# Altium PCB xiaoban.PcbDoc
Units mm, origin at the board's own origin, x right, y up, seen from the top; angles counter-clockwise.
Board outline 80.34 x 99.39 mm, 2 copper layers (Top Layer, Bottom Layer); 120 components, 25 nets, 528 pads, 380 vias.
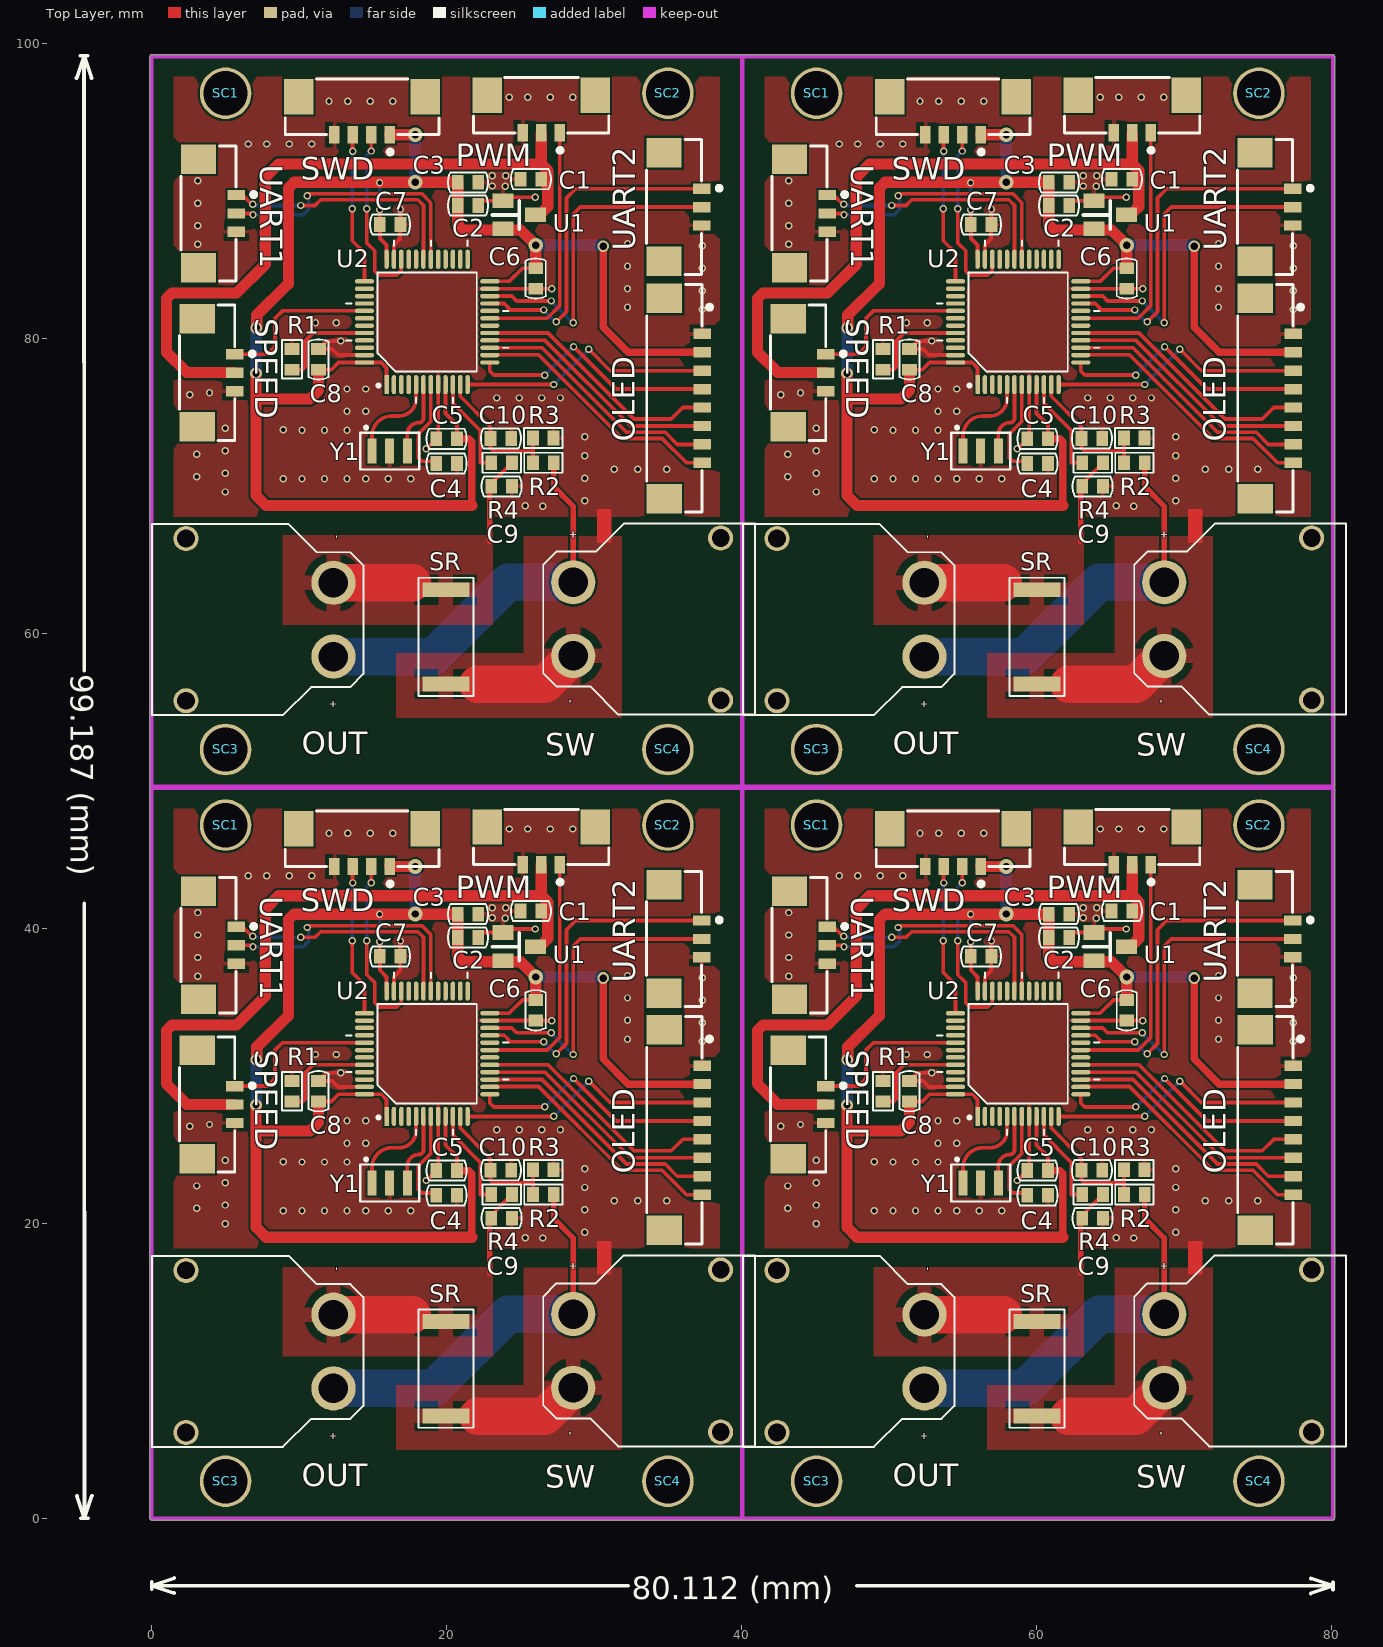
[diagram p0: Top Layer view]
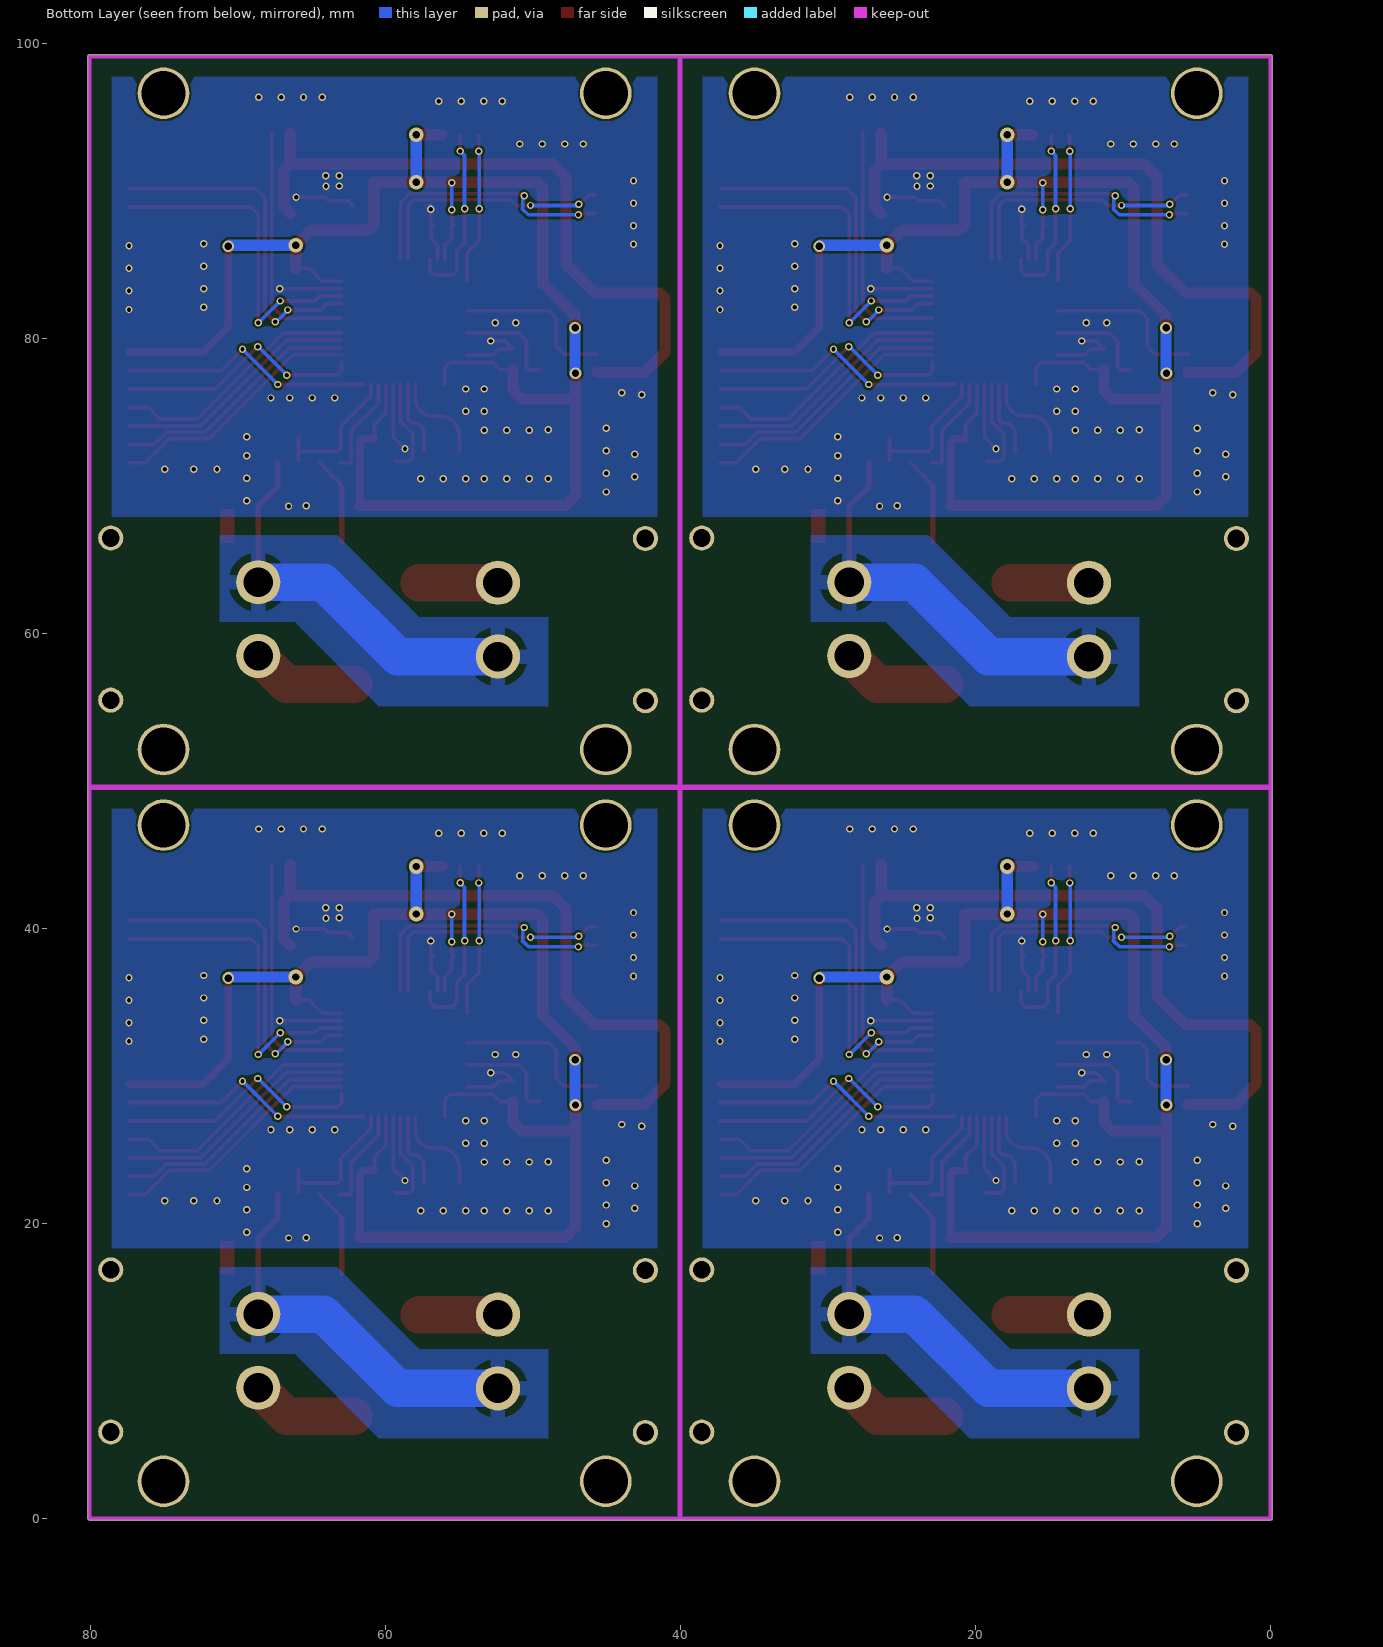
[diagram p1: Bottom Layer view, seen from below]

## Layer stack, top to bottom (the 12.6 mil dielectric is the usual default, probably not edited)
Top Solder: solder mask 0.0102, Solder Resist, Dk 3.5
Top Layer: signal copper 0.0356
Dielectric 1: dielectric 0.32, FR-4, Dk 4.8
Bottom Layer: signal copper 0.0356
Bottom Solder: solder mask 0.0102, Solder Resist, Dk 3.5

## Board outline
-0.127,0 -0.127,49.5 cw(c0,49.5) -0.109,49.566 cw(c0,49.632) -0.127,49.632 -0.127,99.132 cw(c0,99.132) 0,99.259 40,99.259 cw(c40,99.132) 40.041,99.252 cw(c40.081,99.132) 40.081,99.259 80.081,99.259 cw(c80.081,99.132) 80.209,99.132 80.209,49.632 cw(c80.081,49.632) 80.19,49.566 cw(c80.081,49.5) 80.209,49.5 80.209,0 cw(c80.081,0) 80.081,-0.127 40.081,-0.127 cw(c40.081,0) 40.041,-0.121 cw(c40,0) 40,-0.127 0,-0.127 cw(c0,0)

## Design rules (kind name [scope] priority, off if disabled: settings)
Clearance [All] p1: gap=0.152
ComponentClearance [All] p1: gap=0 collisioncheckmode=3 verticalgap=0 showdistances=FALSE
HoleSize [All] p1: absolutevalues=TRUE maxlimit=5 minlimit=0.025 maxpercent=80.000 minpercent=20.000
HoleToHoleClearance [All] p1: gap=0.152 allowstackedmicrovias=TRUE
MinimumSolderMaskSliver [All] p1: minsoldermaskwidth=0
PolygonConnect PolygonConnect_3 [All vs IsVia] p1: connectstyle=Direct reliefconductorwidth=0.254 reliefentries=4 polygonreliefangle="90 Angle" airgapwidth=0.254
PolygonConnect PolygonConnect_2 [All vs (HasFootprint('R2512') OR HasFootprint('TX30-m'))] p2: connectstyle=Relief reliefconductorwidth=1.016 reliefentries=4 polygonreliefangle="90 Angle" airgapwidth=0.508
PolygonConnect PolygonConnect_1 [All vs (InNet('ADC_I') OR InNet('VCC12V'))] p3: connectstyle=Relief reliefconductorwidth=1.27 reliefentries=4 polygonreliefangle="90 Angle" airgapwidth=0.508
PolygonConnect [All] p4: connectstyle=Relief reliefconductorwidth=0.254 reliefentries=4 polygonreliefangle="90 Angle" airgapwidth=0.254
RoutingVias [All] p1: holewidth=0.3 width=0.5 viastyle="Through Hole" minholewidth=0.3 minwidth=0.5 maxholewidth=0.711 maxwidth=1.27
SilkToSilkClearance [All] p1: silktosilkclearance=0
SilkToSolderMaskClearance [IsPad] p1: minsilkscreentomaskgap=0 clearancetoexposedcopper=TRUE
SolderMaskExpansion [All] p1: expansion=0.102
Width [All] p1: maxlimit=5.08 minlimit=0.152 preferedwidth=0.254
24 further rules are at their usual default settings.

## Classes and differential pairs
component class liuyang: C1 C2 C3 C4 C5 C6 C7 C8 C9 C10 OLED OUT PWM R1 R2 R3 R4 SC1 SC2 SC3 SC4 SPEED SR SW SWD U1 U2 UART1 UART2 Y1

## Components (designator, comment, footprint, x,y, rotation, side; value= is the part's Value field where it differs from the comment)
C1 "100n" C0603 25.705,41.173 r180 top
C1 "100n" C0603 25.705,90.805 r180 top
C1 "100n" C0603 65.786,90.805 r180 top
C1 "100n" C0603 65.786,41.173 r180 top
C2 "100n" C0603 21.442,39.387 r0 top
C2 "100n" C0603 21.442,89.019 r0 top
C2 "100n" C0603 61.524,89.019 r0 top
C2 "100n" C0603 61.524,39.387 r0 top
C3 "10UF" C0603 21.442,40.962 r180 top
C3 "10UF" C0603 21.442,90.594 r180 top
C3 "10UF" C0603 61.524,90.594 r180 top
C3 "10UF" C0603 61.524,40.962 r180 top
C4 "0.1uF" C0603 19.99,21.895 r180 top
C4 "0.1uF" C0603 19.99,71.526 r180 top
C4 "0.1uF" C0603 60.071,71.526 r180 top
C4 "0.1uF" C0603 60.071,21.895 r180 top
C5 "10UF" C0603 19.99,23.571 r0 top
C5 "10UF" C0603 19.99,73.203 r0 top
C5 "10UF" C0603 60.071,73.203 r0 top
C5 "10UF" C0603 60.071,23.571 r0 top
C6 "0.1uF" C0603 26.035,34.442 r90 top
C6 "0.1uF" C0603 26.035,84.074 r90 top
C6 "0.1uF" C0603 66.116,84.074 r90 top
C6 "0.1uF" C0603 66.116,34.442 r90 top
C7 "0.1uF" C0603 16.154,38.1 r180 top
C7 "0.1uF" C0603 16.154,87.732 r180 top
C7 "0.1uF" C0603 56.236,87.732 r180 top
C7 "0.1uF" C0603 56.236,38.1 r180 top
C8 "0.1uF" C0603 11.303,28.956 r270 top
C8 "0.1uF" C0603 11.303,78.588 r270 top
C8 "0.1uF" C0603 51.384,78.588 r270 top
C8 "0.1uF" C0603 51.384,28.956 r270 top
C9 "0.1uF" C0603 23.724,20.345 r180 top
C9 "0.1uF" C0603 23.724,69.977 r180 top
C9 "0.1uF" C0603 63.805,69.977 r180 top
C9 "0.1uF" C0603 63.805,20.345 r180 top
C10 "0.1uF" C0603 23.673,23.597 r180 top
C10 "0.1uF" C0603 23.673,73.228 r180 top
C10 "0.1uF" C0603 63.754,73.228 r180 top
C10 "0.1uF" C0603 63.754,23.597 r180 top
OLED "OLED" DF13-1.25-8A 36.043,26.314 r270 top (schematic designator P0)
OLED "OLED" DF13-1.25-8A 36.043,75.946 r270 top (schematic designator P0)
OLED "OLED" DF13-1.25-8A 76.124,75.946 r270 top (schematic designator P0)
OLED "OLED" DF13-1.25-8A 76.124,26.314 r270 top (schematic designator P0)
OUT "TX60" TX30-M 12.319,11.303 r90 top
OUT "TX60" TX30-M 12.319,60.935 r90 top
OUT "TX60" TX30-M 52.4,60.935 r90 top
OUT "TX60" TX30-M 52.4,11.303 r90 top
PWM "Header 3" DF13-1.25-3A 25.781,45.593 r180 top
PWM "Header 3" DF13-1.25-3A 25.781,95.225 r180 top
PWM "Header 3" DF13-1.25-3A 65.862,95.225 r180 top
PWM "Header 3" DF13-1.25-3A 65.862,45.593 r180 top
R1 "10K" R0603 9.5,28.956 r270 top
R1 "10K" R0603 9.5,78.588 r270 top
R1 "10K" R0603 49.581,78.588 r270 top
R1 "10K" R0603 49.581,28.956 r270 top
R2 "10K" R0603 26.554,21.946 r180 top
R2 "10K" R0603 26.554,71.577 r180 top
R2 "10K" R0603 66.635,71.577 r180 top
R2 "10K" R0603 66.635,21.946 r180 top
R3 "10K" R0603 26.543,23.622 r0 top
R3 "10K" R0603 26.543,73.254 r0 top
R3 "10K" R0603 66.624,73.254 r0 top
R3 "10K" R0603 66.624,23.622 r0 top
R4 "10K" R0603 23.724,21.946 r180 top
R4 "10K" R0603 23.724,71.577 r180 top
R4 "10K" R0603 63.805,71.577 r180 top
R4 "10K" R0603 63.805,21.946 r180 top
SC1 "M3" SCRREW_M3 5,47 r0 top
SC1 "M3" SCRREW_M3 5,96.632 r0 top
SC1 "M3" SCRREW_M3 45.081,96.632 r0 top
SC1 "M3" SCRREW_M3 45.081,47 r0 top
SC2 "M3" SCRREW_M3 35,47 r0 top
SC2 "M3" SCRREW_M3 35,96.632 r0 top
SC2 "M3" SCRREW_M3 75.081,96.632 r0 top
SC2 "M3" SCRREW_M3 75.081,47 r0 top
SC3 "M3" SCRREW_M3 5,2.5 r0 top
SC3 "M3" SCRREW_M3 5,52.132 r0 top
SC3 "M3" SCRREW_M3 45.081,52.132 r0 top
SC3 "M3" SCRREW_M3 45.081,2.5 r0 top
SC4 "M3" SCRREW_M3 35,2.5 r0 top
SC4 "M3" SCRREW_M3 35,52.132 r0 top
SC4 "M3" SCRREW_M3 75.081,52.132 r0 top
SC4 "M3" SCRREW_M3 75.081,2.5 r0 top
SPEED "Header 3" DF13-1.25-3A 4.353,27.425 r270 top
SPEED "Header 3" DF13-1.25-3A 4.353,77.056 r270 top
SPEED "Header 3" DF13-1.25-3A 44.435,77.056 r270 top
SPEED "Header 3" DF13-1.25-3A 44.435,27.425 r270 top
SR "0.33R" R2512 19.939,13.335 r270 top
SR "0.33R" R2512 19.939,62.967 r270 top
SR "0.33R" R2512 60.02,62.967 r270 top
SR "0.33R" R2512 60.02,13.335 r270 top
SW "TX30" TX30-M 28.575,11.343 r270 top locked
SW "TX30" TX30-M 28.575,60.975 r270 top locked
SW "TX30" TX30-M 68.656,60.975 r270 top locked
SW "TX30" TX30-M 68.656,11.343 r270 top locked
SWD "CON4" DF13-1.25-4A 14.254,45.476 r180 top
SWD "CON4" DF13-1.25-4A 14.254,95.108 r180 top
SWD "CON4" DF13-1.25-4A 54.335,95.108 r180 top
SWD "CON4" DF13-1.25-4A 54.335,45.476 r180 top
U1 "3.3V" SOT23 24.917,38.76 r270 top
U1 "3.3V" SOT23 24.917,88.392 r270 top
U1 "3.3V" SOT23 64.999,88.392 r270 top
U1 "3.3V" SOT23 64.999,38.76 r270 top
U2 "STM32F103C8" ST_LQFP48 18.669,31.496 r90 top
U2 "STM32F103C8" ST_LQFP48 18.669,81.128 r90 top
U2 "STM32F103C8" ST_LQFP48 58.75,81.128 r90 top
U2 "STM32F103C8" ST_LQFP48 58.75,31.496 r90 top
UART1 "Header 3" DF13-1.25-3A 4.445,38.227 r270 top
UART1 "Header 3" DF13-1.25-3A 4.445,87.859 r270 top
UART1 "Header 3" DF13-1.25-3A 44.526,87.859 r270 top
UART1 "Header 3" DF13-1.25-3A 44.526,38.227 r270 top
UART2 "Header 3" DF13-1.25-3A 36.017,38.659 r270 top
UART2 "Header 3" DF13-1.25-3A 36.017,88.29 r270 top
UART2 "Header 3" DF13-1.25-3A 76.098,88.29 r270 top
UART2 "Header 3" DF13-1.25-3A 76.098,38.659 r270 top
Y1 "CSTCE8M00G55R0" CRYSMD3.2X1.3 16.129,22.733 r0 top
Y1 "CSTCE8M00G55R0" CRYSMD3.2X1.3 16.129,72.365 r0 top
Y1 "CSTCE8M00G55R0" CRYSMD3.2X1.3 56.21,72.365 r0 top
Y1 "CSTCE8M00G55R0" CRYSMD3.2X1.3 56.21,22.733 r0 top

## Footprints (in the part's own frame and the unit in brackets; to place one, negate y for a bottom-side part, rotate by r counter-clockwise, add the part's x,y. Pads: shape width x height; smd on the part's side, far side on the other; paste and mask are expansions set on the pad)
C0603 [mm]
  rect 0.8x1 smd: 1(-0.7,0) 2(0.7,0)
  Top Layer pour cut-out: -0.3,0.5 -0.3,-0.5 0.3,-0.5 0.3,0.5
  silkscreen extent -1.36,-0.68 1.36,0.68
CRYSMD3.2X1.3 [mm]
  rect 0.6x1.7 smd: 1(-1.2,0) 2(0,0) 3(1.2,0)
  Top Layer pour cut-out: -1.625,0.8 -0.406,0.8 -0.406,-0.8 -1.625,-0.8
  Top Layer pour cut-out: 0.394,0.8 1.613,0.8 1.613,-0.8 0.394,-0.8
  silkscreen extent -2,-1.25 2,1.7
DF13-1.25-3A [mm] "佳能"
  rect 0.7x1.18 smd: 1(-1.875,1.28) 2(-0.625,1.28) 3(0.625,1.28)
  rect 2x2.4 smd: NC(-4.3,-1.28) NC(3.05,-1.28)
  silkscreen extent -5.21,-2.48 3.96,2.61
DF13-1.25-4A [mm] "佳能"
  rect 0.7x1.18 smd: 1(-1.875,1.28) 2(-0.625,1.28) 3(0.625,1.28) 4(1.875,1.28)
  rect 2x2.4 smd: NC(-4.3,-1.28) NC(4.3,-1.28)
  silkscreen extent -5.21,-2.48 5.21,2.61
DF13-1.25-8A [mm]
  rect 0.7x1.18 smd: 1(-4.375,1.28) 2(-3.125,1.28) 3(-1.875,1.28) 4(-0.625,1.28) 5(0.625,1.28) 6(1.875,1.28) 7(3.125,1.28) 8(4.375,1.28)
  rect 2x2.4 smd: NC(-6.8,-1.28) NC(6.8,-1.28)
  silkscreen extent -7.71,-2.48 7.71,1.93
R0603 [mm]
  rect 0.8x1 smd: 1(-0.7,0) 2(0.7,0)
  Top Layer pour cut-out: -0.3,0.5 -0.3,-0.5 0.3,-0.5 0.3,0.5
  silkscreen extent -1.3,-0.68 1.3,0.68
R2512 [mm]
  rect 1x3.2 smd: 1(0,0) 2(6.4,0)
  silkscreen extent -0.81,-1.85 7.2,1.87
SCRREW_M3 [mm]
  round 3.5 hole 3: 0(0,0)
SOT23 [mm] "SOT23"
  rect 1x1.4 smd: 1(-0.95,-1.1) 2(0.95,-1.1) 3(0,1.1)
  silkscreen extent -0.94,-1.82 0.97,0
ST_LQFP48 [mm]
  rect 1.3x0.3 smd: 1(-4.25,2.75)
  oval 1.3x0.3 smd: 2(-4.25,2.25) 3(-4.25,1.75) 4(-4.25,1.25) 5(-4.25,0.75) 6(-4.25,0.25) 7(-4.25,-0.25) 8(-4.25,-0.75) 9(-4.25,-1.25) 10(-4.25,-1.75) 11(-4.25,-2.25) 12(-4.25,-2.75) 25(4.25,-2.75) 26(4.25,-2.25) 27(4.25,-1.75) 28(4.25,-1.25) 29(4.25,-0.75) 30(4.25,-0.25) 31(4.25,0.25) 32(4.25,0.75) 33(4.25,1.25) 34(4.25,1.75) 35(4.25,2.25) 36(4.25,2.75)
  oval 0.3x1.3 smd: 13(-2.75,-4.25) 14(-2.25,-4.25) 15(-1.75,-4.25) 16(-1.25,-4.25) 17(-0.75,-4.25) 18(-0.25,-4.25) 19(0.25,-4.25) 20(0.75,-4.25) 21(1.25,-4.25) 22(1.75,-4.25) 23(2.25,-4.25) 24(2.75,-4.25) 37(2.75,4.25) 38(2.25,4.25) 39(1.75,4.25) 40(1.25,4.25) 41(0.75,4.25) 42(0.25,4.25) 43(-0.25,4.25) 44(-0.75,4.25) 45(-1.25,4.25) 46(-1.75,4.25) 47(-2.25,4.25) 48(-2.75,4.25)
  silkscreen extent -5.52,-5.52 5.52,5.52
TX30-M [mm]
  round 1.7 hole 1.2: 0(-5.5,10) 0(5.5,10)
  round 3 hole 2: 1(-2.5,0) 2(2.5,0)
  silkscreen extent -6.48,-2.03 6.48,12.32

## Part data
C1 C1 C1 C1 C2 C2 C2 C2: library part C-EUC0603, "CAPACITOR, European symbol"
C3 C3 C3 C3 C4 C4 C4 C4 C5 C5 C5 C5 C6 C6 C6 C6 C7 C7 C7 C7 C8 C8 C8 C8 C9 C9 C9 C9 C10 C10 C10 C10: library part Cap, "Capacitor"
OLED OLED OLED OLED: library part "Header 8", "Header, 8-Pin"
OUT OUT OUT OUT SW SW SW SW: library part "Header 2", "Header, 2-Pin"
PWM PWM PWM PWM SPEED SPEED SPEED SPEED UART1 UART1 UART1 UART1 UART2 UART2 UART2 UART2: "Header, 3-Pin"
R1 R1 R1 R1 R2 R2 R2 R2 R3 R3 R3 R3 R4 R4 R4 R4: library part Res2, "Resistor"
SC1 SC1 SC1 SC1 SC2 SC2 SC2 SC2 SC3 SC3 SC3 SC3 SC4 SC4 SC4 SC4: library part Screw_M3, "Screw"
SR SR SR SR: library part R-EU_R0603, "RESISTOR, European symbol"
U1 U1 U1 U1: library part XC6206
Y1 Y1 Y1 Y1: library part XTAL-3

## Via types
v1: diameter 0.5, hole 0.3, Top Layer to Bottom Layer, tented both sides, 356 vias
v2: diameter 0.8, hole 0.5, Top Layer to Bottom Layer, tented both sides, 12 vias
v3: diameter 1, hole 0.5, Top Layer to Bottom Layer, tented both sides, 12 vias

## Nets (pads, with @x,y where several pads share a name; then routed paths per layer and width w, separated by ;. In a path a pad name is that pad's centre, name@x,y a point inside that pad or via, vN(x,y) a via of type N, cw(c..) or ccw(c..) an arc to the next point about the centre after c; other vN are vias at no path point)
ADC_C: C10.2@22.973,23.597 R2.2@25.854,21.946 R3.1@25.843,23.622 U2.11@20.919,27.246 | length 9.6
  Top Layer w0.254: U2.11@20.919,27.246 20.919,26.452 22.973,24.398 22.973,23.597 22.973,22.925 23.165,22.733 25.843,22.733 ; R2.2@25.843,22.098 25.843,22.733 ; R3.1@25.843,23.622 25.843,22.733
ADC_I: R4.2@23.024,21.946 U2.10@20.419,27.246 | length 6.8
  Top Layer w0.254: U2.10@20.419,27.246 20.419,25.987 22.276,24.13 22.276,21.946 R4.2@23.024,21.946
BL: OLED.3@37.323,28.189 U2.12@21.419,27.246 | length 17.5
  Top Layer w0.254: U2.12@21.419,27.246 v1@27.237,27.246 ; v1(29.642,29.642) 31.094,28.189 OLED.3@37.323,28.189
  Bottom Layer w0.254: v1(27.254,27.254) v1(29.642,29.642)
CS: OLED.8@37.323,21.94 U2.14@22.919,29.246 | length 17.5
  Top Layer w0.254: U2.14@22.919,29.246 22.948,29.275 26.224,29.275 31.902,23.597 34.595,23.597 36.252,21.94 OLED.8@37.323,21.94
GND: C1.2@25.005,41.173 C2.2@22.142,39.387 C3.1@22.142,40.962 C4.1@20.69,21.895 C5.1@19.29,23.571 C6.1@26.035,33.742 C7.1@16.854,38.1 C8.1@11.303,29.656 C9.1@24.424,20.345 C10.1@24.373,23.597 OLED.1@37.323,30.689 PWM.3@25.156,44.313 R1.1@9.5,29.656 R3.2@27.243,23.622 SPEED.3@5.633,26.8 SR.2@19.939,6.935 SW.2@28.575,8.843 SWD.4@12.379,44.196 U1.1@23.817,39.71 U2.8@19.419,27.246 U2.23@22.919,33.746 U2.35@16.419,35.746 U2.47@14.419,29.246 UART1.3@5.725,37.602 UART2.3@37.297,38.034 Y1.2@16.129,22.733 | length 29.4
  Top Layer w0.254: v1(12.802,30.201) 11.848,30.201 11.303,29.656 12.229,29.656 12.639,29.246 U2.47@14.419,29.246 ; U2.35@16.419,35.746 16.419,36.714 16.854,37.149 C7.1@16.854,37.948 ; C7.1@16.702,38.1 C7.1@16.854,37.948 ; v1(16.866,39.141) 16.866,38.111 16.854,38.1 C7.1@16.854,37.948 ; v1(18.618,22.9) 19.29,23.571 19.419,23.7 U2.8@19.419,27.246 ; C2.2@22.142,39.387 22.465,39.71 23.817,39.71 24.061,39.954 v1(26.01,39.954) ; U2.23@22.919,33.746 26.031,33.746 26.035,33.742 v1(27.113,33.742)
  Top Layer w2.54: 22.098,6.909 26.641,6.909 SW.2@28.575,8.843
  Bottom Layer w0.254: v1(12.802,30.201) v1@12.852,30.15 ; v1(16.866,39.141) 16.866,39.319 v1@16.916,39.37 ; v1(27.113,33.742) v1@27.127,33.757
  other v1: 26.518,18.999 25.324,19.025 29.362,19.38 4.978,19.964 8.915,20.853 10.185,20.853 11.709,20.853 13.233,20.853 14.503,20.853 16.027,20.853 17.551,20.853 29.362,20.904 3.048,21.006 4.978,21.234 31.369,21.514 32.944,21.514 34.925,21.514 29.362,22.428 3.048,22.53 4.978,22.758 29.362,23.698 10.185,24.155 11.709,24.155 13.233,24.155 8.915,24.181 4.978,24.282 13.233,25.425 14.503,25.425 23.393,26.34 24.917,26.34 26.441,26.34 27.711,26.34 2.565,26.568 3.912,26.695 13.233,26.949 14.503,26.949 11.1,31.445 12.497,31.445 37.338,32.334 32.258,32.487 37.338,33.604 32.258,33.757 37.338,35.128 32.258,35.281 37.338,36.652 3.124,36.754 32.258,36.805 3.124,38.024 3.124,39.548 23.978,40.691 23.089,40.716 3.124,41.072 23.089,41.402 24.003,41.402 6.528,43.561 7.798,43.561 9.322,43.561 10.846,43.561 12.014,46.457 13.284,46.457 14.808,46.457 16.332,46.457 24.232,46.736 25.502,46.736 27.026,46.736 28.55,46.736
MISO: OLED.6@37.323,24.439 U2.16@22.919,30.246 | length 16.8
  Top Layer w0.254: U2.16@22.919,30.246 26.667,30.246 32.474,24.439 OLED.6@37.323,24.439
MOSI: OLED.5@37.323,25.689 U2.17@22.919,30.746 | length 17.1
  Top Layer w0.254: U2.17@22.919,30.746 26.874,30.746 32.703,24.917 35.23,24.917 36.002,25.689 OLED.5@37.323,25.689
NetC9_2: C9.2@23.024,20.345 OUT.2@12.319,13.803 R4.1@24.424,21.946 SR.1@19.939,13.335 | length 11.3
  Top Layer w0.254: C9.2@23.024,20.345 23.024,20.546 R4.1@24.424,21.946
  Top Layer w0.381: 22.922,16.6 C9.2@22.922,20.345
  Top Layer w2.54: OUT.2@12.319,13.803 17.653,13.803
NetR1_2: R1.2@9.5,28.256 U2.44@14.419,30.746 | length 7
  Top Layer w0.254: R1.2@9.5,28.256 10.222,28.256 10.389,28.423 10.389,30.201 10.934,30.746 U2.44@14.419,30.746
NetU2_5: U2.5@17.919,27.246 Y1.1@14.929,22.733 | length 6.4
  Top Layer w0.254: Y1.1@14.929,22.733 14.929,23.768 cw(c16.281,23.768) 16.281,25.121 16.764,25.121 ccw(c16.764,26.276) 17.919,26.276 U2.5@17.919,27.246
NetU2_6: U2.6@18.419,27.246 Y1.3@17.329,22.733 | length 5.1
  Top Layer w0.254: Y1.3@17.329,22.733 17.329,23.882 cw(c18.11,23.882) 18.11,24.663 ccw(c18.11,24.972) 18.419,24.972 U2.6@18.419,27.246
PWN0: PWM.1@27.656,44.313 U2.19@22.919,31.746 | length 16.8
  Top Layer w0.254: U2.19@22.919,31.746 26.818,31.746 27.656,32.584 PWM.1@27.656,44.313
REST1: C4.2@19.29,21.895 U2.7@18.919,27.246 | length 6.6
  Top Layer w0.254: U2.7@18.919,27.246 18.919,24.736 18.089,23.905 18.089,22.272 18.313,22.047 C4.2@19.29,22.047
RS: OLED.4@37.323,26.939 U2.13@22.919,28.746 | length 17.1
  Top Layer w0.254: U2.13@22.919,28.746 22.919,28.16 23.19,27.889 v1(26.645,27.889) ; v1(28.6,29.82) 31.481,26.939 OLED.4@37.323,26.939
  Bottom Layer w0.254: v1(26.645,27.889) 28.575,29.82 v1(28.6,29.82)
RX1: U2.31@18.419,35.746 UART1.1@5.725,40.102 | length 17
  Top Layer w0.254: UART1.1@5.725,40.102 6.151,40.102 6.782,39.472 v1(6.833,39.472) ; v1(10.109,39.395) 11.074,39.395 11.455,39.776 18.034,39.776 18.419,39.391 U2.31@18.419,35.746
  Bottom Layer w0.254: v1(6.833,39.472) 6.833,39.421 6.858,39.395 v1(10.109,39.395)
RX2: U2.22@22.919,33.246 UART2.2@37.297,39.284 | length 22.7
  Top Layer w0.254: U2.22@22.919,33.246 24.412,33.246 24.74,32.918 v1(27.076,32.918) ; v1(28.575,31.445) 28.575,38.811 29.048,39.284 UART2.2@37.297,39.284
  Bottom Layer w0.254: v1(27.076,32.918) 28.55,31.445 v1(28.575,31.445)
SCK: OLED.7@37.323,23.19 U2.15@22.919,29.746 | length 17.1
  Top Layer w0.254: U2.15@22.919,29.746 26.46,29.746 32.192,24.014 34.813,24.014 35.637,23.19 OLED.7@37.323,23.19
SPEED: SPEED.1@5.633,29.3 U2.41@14.419,32.246 | length 11.2
  Top Layer w0.254: SPEED.1@5.598,29.307 7.844,29.307 8.357,29.82 8.357,31.75 8.853,32.246 U2.41@14.419,32.246
SWCLK: SWD.3@13.629,44.196 U2.37@14.419,34.246 | length 10.4
  Top Layer w0.254: v1(13.589,39.167) 13.589,37.008 14.419,36.178 U2.37@14.419,34.246 ; v1(13.614,43.078) 13.614,44.058 13.691,44.134 SWD.3@13.629,44.196
  Bottom Layer w0.254: v1(13.589,39.167) 13.589,43.002 13.64,43.053 v1(13.614,43.078)
SWDIO: SWD.2@14.879,44.196 U2.34@16.919,35.746 | length 12.4
  Top Layer w0.254: v1(14.58,39.167) 14.58,36.855 15.113,36.322 15.113,34.95 15.39,34.674 16.612,34.674 16.919,34.981 U2.34@16.919,35.746 ; v1(14.879,43.084) SWD.2@14.879,44.196
  Bottom Layer w0.254: v1(14.58,39.167) 14.58,42.785 v1(14.879,43.084)
TX1: U2.30@18.919,35.746 UART1.2@5.725,38.852 | length 18.6
  Top Layer w0.254: UART1.2@5.725,38.852 6.792,38.852 6.858,38.786 v1(6.858,38.76) ; v1(10.541,40.056) 10.668,40.183 18.313,40.183 18.919,39.577 U2.30@18.919,35.746
  Bottom Layer w0.254: v1(6.858,38.76) 10.266,38.76 10.647,39.141 10.639,39.149 10.639,39.958 v1(10.541,40.056)
TX2: U2.21@22.919,32.746 UART2.1@37.297,40.534 | length 23.1
  Top Layer w0.254: U2.21@22.919,32.746 23.896,32.746 24.333,32.309 v1(26.568,32.309) ; v1(27.432,31.496) 28.118,32.182 28.118,39.903 28.748,40.534 UART2.1@37.297,40.534
  Bottom Layer w0.254: v1@26.594,32.258 27.356,31.496 v1(27.432,31.496)
VCC12V: OUT.1@12.319,8.803 R2.1@27.254,21.946 SW.1@28.575,13.843 | length 27
  Top Layer w0.381: R2.1@27.254,21.946 27.254,20.32 28.575,18.999 SW.1@28.575,13.843
  Bottom Layer w2.54: OUT.1@12.319,8.803 19.115,8.803 24.155,13.843 SW.1@28.575,13.843
VDD_3V3: C2.1@20.742,39.387 C3.2@20.742,40.962 C5.2@20.69,23.571 C6.2@26.035,35.142 C7.2@15.454,38.1 C8.2@11.303,28.256 OLED.2@37.323,29.439 SWD.1@16.129,44.196 U1.2@23.817,37.81 U2.1@15.919,27.246 U2.9@19.919,27.246 U2.24@22.919,34.246 U2.36@15.919,35.746 U2.48@14.419,28.746 | length 111.5
  Top Layer w0.254: C8.2@11.303,28.256 12.178,28.256 12.668,28.746 14.419,28.746 15.552,28.746 15.919,28.379 U2.1@15.919,27.246 ; C7.2@15.302,38.1 15.469,37.933 15.469,37.16 15.919,36.71 U2.36@15.919,35.746 ; C7.2@15.454,38.1 v1(15.454,39.102) ; U2.9@19.919,27.246 19.919,25.293 20.69,24.522 C5.2@20.69,23.571 ; U2.24@22.919,34.246 24.232,34.246 25.128,35.142 C6.2@26.035,35.142
  Top Layer w0.508: C5.2@20.69,23.571 21.488,23.571 21.692,23.368 21.692,19.05 ; v2(30.607,36.627) 30.607,31.14 32.308,29.439 OLED.2@37.323,29.439
  Top Layer w0.762: v2(7.061,28.016) 7.061,26.264 ; v2(7.087,31.09) 7.112,31.115 7.112,31.953 9.22,34.061 9.271,34.061 9.271,40.589 9.644,40.962 17.856,40.962 20.742,40.962 20.742,39.387 20.742,38.084 21.092,37.734 25.004,37.734 v3(26.035,36.703) C6.2@26.035,35.142 ; C8.2@11.303,28.256 11.303,26.848 10.719,26.264 7.061,26.264 ; SWD.1@16.129,44.196 v3(17.856,44.196) ; 21.692,19.05 7.747,19.05 7.061,19.736 7.061,26.264
  Bottom Layer w0.254: v1(15.443,40.945) 15.454,40.934 v1(15.454,39.102)
  Bottom Layer w0.762: v2(7.061,28.016) v2@7.087,28.042 ; v2@7.087,28.016 v2@7.087,28.042 ; v2(7.087,31.09) v2@7.087,28.042 ; v3(17.856,40.97) v3(17.856,44.196) ; v3(26.035,36.703) 30.531,36.703 v2(30.607,36.627)
VIN: C1.1@26.405,41.173 PWM.2@26.406,44.313 SPEED.2@5.633,28.05 U1.3@26.017,38.76 | length 47.3
  Top Layer w0.762: SPEED.2@5.598,28.057 2.372,28.057 0.991,29.439 0.991,33.071 1.372,33.452 5.74,33.452 7.696,35.408 7.696,41.326 8.585,42.215 26.406,42.215 ; U1.3@26.379,38.843 26.848,39.311 26.848,41.773 26.406,42.215 ; PWM.2@26.406,44.313 26.406,42.215
pads on no net: C1.1@26.405,90.805 C1.1@66.486,41.173 C1.1@66.486,90.805 C1.2@25.005,90.805 C1.2@65.086,41.173 C1.2@65.086,90.805 C2.1@20.742,89.019 C2.1@60.824,39.387 C2.1@60.824,89.019 C2.2@22.142,89.019 C2.2@62.224,39.387 C2.2@62.224,89.019 C3.1@22.142,90.594 C3.1@62.224,40.962 C3.1@62.224,90.594 C3.2@20.742,90.594 C3.2@60.824,40.962 C3.2@60.824,90.594 C4.1@20.69,71.526 C4.1@60.771,21.895 C4.1@60.771,71.526 C4.2@19.29,71.526 C4.2@59.371,21.895 C4.2@59.371,71.526 C5.1@19.29,73.203 C5.1@59.371,23.571 C5.1@59.371,73.203 C5.2@20.69,73.203 C5.2@60.771,23.571 C5.2@60.771,73.203 C6.1@26.035,83.374 C6.1@66.116,33.742 C6.1@66.116,83.374 C6.2@26.035,84.774 C6.2@66.116,35.142 C6.2@66.116,84.774 C7.1@16.854,87.732 C7.1@56.936,38.1 C7.1@56.936,87.732 C7.2@15.454,87.732 C7.2@55.536,38.1 C7.2@55.536,87.732 C8.1@11.303,79.288 C8.1@51.384,29.656 C8.1@51.384,79.288 C8.2@11.303,77.888 C8.2@51.384,28.256 C8.2@51.384,77.888 C9.1@24.424,69.977 C9.1@64.505,20.345 C9.1@64.505,69.977 C9.2@23.024,69.977 C9.2@63.105,20.345 C9.2@63.105,69.977 C10.1@24.373,73.228 C10.1@64.454,23.597 C10.1@64.454,73.228 C10.2@22.973,73.228 C10.2@63.054,23.597 C10.2@63.054,73.228 OLED.1@37.323,80.321 OLED.1@77.404,30.689 OLED.1@77.404,80.321 OLED.2@37.323,79.071 OLED.2@77.404,29.439 OLED.2@77.404,79.071 OLED.3@37.323,77.821 OLED.3@77.404,28.189 OLED.3@77.404,77.821 OLED.4@37.323,76.571 OLED.4@77.404,26.939 OLED.4@77.404,76.571 OLED.5@37.323,75.321 OLED.5@77.404,25.689 OLED.5@77.404,75.321 OLED.6@37.323,74.071 OLED.6@77.404,24.439 OLED.6@77.404,74.071 OLED.7@37.323,72.821 OLED.7@77.404,23.19 OLED.7@77.404,72.821 OLED.8@37.323,71.571 OLED.8@77.404,21.94 OLED.8@77.404,71.571 OLED.NC OUT.0 OUT.1@12.319,58.435 OUT.1@52.4,8.803 OUT.1@52.4,58.435 OUT.2@12.319,63.435 OUT.2@52.4,13.803 OUT.2@52.4,63.435 PWM.1@27.656,93.945 PWM.1@67.737,44.313 PWM.1@67.737,93.945 PWM.2@26.406,93.945 PWM.2@66.487,44.313 PWM.2@66.487,93.945 PWM.3@25.156,93.945 PWM.3@65.237,44.313 PWM.3@65.237,93.945 PWM.NC R1.1@9.5,79.288 R1.1@49.581,29.656 R1.1@49.581,79.288 R1.2@9.5,77.888 R1.2@49.581,28.256 R1.2@49.581,77.888 R2.1@27.254,71.577 R2.1@67.335,21.946 R2.1@67.335,71.577 R2.2@25.854,71.577 R2.2@65.935,21.946 R2.2@65.935,71.577 R3.1@25.843,73.254 R3.1@65.924,23.622 R3.1@65.924,73.254 R3.2@27.243,73.254 R3.2@67.324,23.622 R3.2@67.324,73.254 R4.1@24.424,71.577 R4.1@64.505,21.946 R4.1@64.505,71.577 R4.2@23.024,71.577 R4.2@63.105,21.946 R4.2@63.105,71.577 SC1.0 SC2.0 SC3.0 SC4.0 SPEED.1@5.633,78.931 SPEED.1@45.715,29.3 SPEED.1@45.715,78.931 SPEED.2@5.633,77.681 SPEED.2@45.715,28.05 SPEED.2@45.715,77.681 SPEED.3@5.633,76.431 SPEED.3@45.715,26.8 SPEED.3@45.715,76.431 SPEED.NC SR.1@19.939,62.967 SR.1@60.02,13.335 SR.1@60.02,62.967 SR.2@19.939,56.567 SR.2@60.02,6.935 SR.2@60.02,56.567 SW.0 SW.1@28.575,63.475 SW.1@68.656,13.843 SW.1@68.656,63.475 SW.2@28.575,58.475 SW.2@68.656,8.843 SW.2@68.656,58.475 SWD.1@16.129,93.828 SWD.1@56.21,44.196 SWD.1@56.21,93.828 SWD.2@14.879,93.828 SWD.2@54.96,44.196 SWD.2@54.96,93.828 SWD.3@13.629,93.828 SWD.3@53.71,44.196 SWD.3@53.71,93.828 SWD.4@12.379,93.828 SWD.4@52.46,44.196 SWD.4@52.46,93.828 SWD.NC U1.1@23.817,89.342 U1.1@63.899,39.71 U1.1@63.899,89.342 U1.2@23.817,87.442 U1.2@63.899,37.81 U1.2@63.899,87.442 U1.3@26.017,88.392 U1.3@66.099,38.76 U1.3@66.099,88.392 U2.1@15.919,76.878 U2.1@56,27.246 U2.1@56,76.878 U2.2 U2.3 U2.4 U2.5@17.919,76.878 U2.5@58,27.246 U2.5@58,76.878 U2.6@18.419,76.878 U2.6@58.5,27.246 U2.6@58.5,76.878 U2.7@18.919,76.878 U2.7@59,27.246 U2.7@59,76.878 U2.8@19.419,76.878 U2.8@59.5,27.246 U2.8@59.5,76.878 U2.9@19.919,76.878 U2.9@60,27.246 U2.9@60,76.878 U2.10@20.419,76.878 U2.10@60.5,27.246 U2.10@60.5,76.878 U2.11@20.919,76.878 U2.11@61,27.246 U2.11@61,76.878 U2.12@21.419,76.878 U2.12@61.5,27.246 U2.12@61.5,76.878 U2.13@22.919,78.378 U2.13@63,28.746 U2.13@63,78.378 U2.14@22.919,78.878 U2.14@63,29.246 U2.14@63,78.878 U2.15@22.919,79.378 U2.15@63,29.746 U2.15@63,79.378 U2.16@22.919,79.878 U2.16@63,30.246 U2.16@63,79.878 U2.17@22.919,80.378 U2.17@63,30.746 U2.17@63,80.378 U2.18 U2.19@22.919,81.378 U2.19@63,31.746 U2.19@63,81.378 U2.20 U2.21@22.919,82.378 U2.21@63,32.746 U2.21@63,82.378 U2.22@22.919,82.878 U2.22@63,33.246 U2.22@63,82.878 U2.23@22.919,83.378 U2.23@63,33.746 U2.23@63,83.378 U2.24@22.919,83.878 U2.24@63,34.246 U2.24@63,83.878 U2.25 U2.26 U2.27 U2.28 U2.29 U2.30@18.919,85.378 U2.30@59,35.746 U2.30@59,85.378 U2.31@18.419,85.378 U2.31@58.5,35.746 U2.31@58.5,85.378 U2.32 U2.33 U2.34@16.919,85.378 U2.34@57,35.746 U2.34@57,85.378 U2.35@16.419,85.378 U2.35@56.5,35.746 U2.35@56.5,85.378 U2.36@15.919,85.378 U2.36@56,35.746 U2.36@56,85.378 U2.37@14.419,83.878 U2.37@54.5,34.246 U2.37@54.5,83.878 U2.38 U2.39 U2.40 U2.41@14.419,81.878 U2.41@54.5,32.246 U2.41@54.5,81.878 U2.42 U2.43 U2.44@14.419,80.378 U2.44@54.5,30.746 U2.44@54.5,80.378 U2.45 U2.46 U2.47@14.419,78.878 U2.47@54.5,29.246 U2.47@54.5,78.878 U2.48@14.419,78.378 U2.48@54.5,28.746 U2.48@54.5,78.378 UART1.1@5.725,89.734 UART1.1@45.806,40.102 UART1.1@45.806,89.734 UART1.2@5.725,88.484 UART1.2@45.806,38.852 UART1.2@45.806,88.484 UART1.3@5.725,87.234 UART1.3@45.806,37.602 UART1.3@45.806,87.234 UART1.NC UART2.1@37.297,90.166 UART2.1@77.378,40.534 UART2.1@77.378,90.166 UART2.2@37.297,88.915 UART2.2@77.378,39.284 UART2.2@77.378,88.915 UART2.3@37.297,87.665 UART2.3@77.378,38.034 UART2.3@77.378,87.665 UART2.NC Y1.1@14.929,72.365 Y1.1@55.01,22.733 Y1.1@55.01,72.365 Y1.2@16.129,72.365 Y1.2@56.21,22.733 Y1.2@56.21,72.365 Y1.3@17.329,72.365 Y1.3@57.41,22.733 Y1.3@57.41,72.365
copper on no net: | length 1510
  Top Layer w0.254: 5.598,78.939 7.844,78.939 8.357,79.451 8.357,81.382 8.853,81.878 14.419,81.878 ; 5.725,88.484 6.792,88.484 6.858,88.417 v1(6.858,88.392) ; 5.725,89.734 6.151,89.734 6.782,89.103 v1(6.833,89.103) ; 9.5,77.888 10.222,77.888 10.389,78.054 10.389,79.832 10.934,80.378 14.419,80.378 ; v1(10.109,89.027) 11.074,89.027 11.455,89.408 18.034,89.408 18.419,89.023 18.419,85.378 ; v1(10.541,89.687) 10.668,89.814 18.313,89.814 18.919,89.209 18.919,85.378 ; 11.303,77.888 12.178,77.888 12.668,78.378 14.419,78.378 15.552,78.378 15.919,78.01 15.919,76.878 ; v1(12.802,79.832) 11.848,79.832 11.303,79.288 12.229,79.288 12.639,78.878 14.419,78.878 ; v1(13.589,88.798) 13.589,86.639 14.419,85.809 14.419,83.878 ; v1(13.614,92.71) 13.614,93.69 13.691,93.766 13.629,93.828 ; v1(14.58,88.798) 14.58,86.487 15.113,85.954 15.113,84.582 15.39,84.305 16.612,84.305 16.919,84.613 16.919,85.378 ; v1(14.879,92.716) 14.879,93.828 ; 14.929,72.365 14.929,73.4 cw(c16.281,73.4) 16.281,74.752 16.764,74.752 ccw(c16.764,75.907) 17.919,75.907 17.919,76.878 ; 15.302,87.732 15.469,87.565 15.469,86.792 15.919,86.341 15.919,85.378 ; 15.454,87.732 v1(15.454,88.733) ; 16.419,85.378 16.419,86.345 16.854,86.781 16.854,87.579 ; 16.702,87.732 16.854,87.579 ; v1(16.866,88.773) 16.866,87.743 16.854,87.732 16.854,87.579 ; 17.329,72.365 17.329,73.514 cw(c18.11,73.514) 18.11,74.295 ccw(c18.11,74.604) 18.419,74.604 18.419,76.878 ; v1(18.618,72.531) 19.29,73.203 19.419,73.332 19.419,76.878 ; 18.919,76.878 18.919,74.367 18.089,73.537 18.089,71.903 18.313,71.679 19.29,71.679 ; 19.919,76.878 19.919,74.925 20.69,74.154 20.69,73.203 ; 20.419,76.878 20.419,75.618 22.276,73.762 22.276,71.577 23.024,71.577 ; 20.919,76.878 20.919,76.084 22.973,74.03 22.973,73.228 22.973,72.557 23.165,72.365 25.843,72.365 ; 21.419,76.878 v1@27.237,76.878 ; 22.142,89.019 22.465,89.342 23.817,89.342 24.061,89.586 v1(26.01,89.586) ; 22.919,78.378 22.919,77.792 23.19,77.521 v1(26.645,77.521) ; 22.919,78.878 22.948,78.907 26.224,78.907 31.902,73.228 34.595,73.228 36.252,71.571 37.323,71.571 ; 22.919,79.378 26.46,79.378 32.192,73.645 34.813,73.645 35.637,72.821 37.323,72.821 ; 22.919,79.878 26.667,79.878 32.474,74.071 37.323,74.071 ; 22.919,80.378 26.874,80.378 32.703,74.549 35.23,74.549 36.002,75.321 37.323,75.321 ; 22.919,81.378 26.818,81.378 27.656,82.215 27.656,93.945 ; 22.919,82.378 23.896,82.378 24.333,81.94 v1(26.568,81.94) ; 22.919,82.878 24.412,82.878 24.74,82.55 v1(27.076,82.55) ; 22.919,83.378 26.031,83.378 26.035,83.374 v1(27.113,83.374) ; 22.919,83.878 24.232,83.878 25.128,84.774 26.035,84.774 ; 23.024,69.977 23.024,70.177 24.424,71.577 ; 25.843,71.73 25.843,72.365 ; 25.843,73.254 25.843,72.365 ; v1(27.432,81.128) 28.118,81.813 28.118,89.535 28.748,90.166 37.297,90.166 ; v1(28.575,81.077) 28.575,88.443 29.048,88.915 37.297,88.915 ; v1(28.6,79.451) 31.481,76.571 37.323,76.571 ; v1(29.642,79.273) 31.094,77.821 37.323,77.821 ; 45.679,29.307 47.925,29.307 48.438,29.82 48.438,31.75 48.934,32.246 54.5,32.246 ; 45.679,78.939 47.925,78.939 48.438,79.451 48.438,81.382 48.934,81.878 54.5,81.878 ; 45.806,38.852 46.873,38.852 46.939,38.786 v1(46.939,38.76) ; 45.806,40.102 46.232,40.102 46.863,39.472 v1(46.914,39.472) ; 45.806,88.484 46.873,88.484 46.939,88.417 v1(46.939,88.392) ; 45.806,89.734 46.232,89.734 46.863,89.103 v1(46.914,89.103) ; 49.581,28.256 50.303,28.256 50.47,28.423 50.47,30.201 51.015,30.746 54.5,30.746 ; 49.581,77.888 50.303,77.888 50.47,78.054 50.47,79.832 51.015,80.378 54.5,80.378 ; v1(50.19,39.395) 51.156,39.395 51.537,39.776 58.115,39.776 58.5,39.391 58.5,35.746 ; v1(50.19,89.027) 51.156,89.027 51.537,89.408 58.115,89.408 58.5,89.023 58.5,85.378 ; v1(50.622,40.056) 50.749,40.183 58.395,40.183 59,39.577 59,35.746 ; v1(50.622,89.687) 50.749,89.814 58.395,89.814 59,89.209 59,85.378 ; 51.384,28.256 52.259,28.256 52.749,28.746 54.5,28.746 55.633,28.746 56,28.379 56,27.246 ; 51.384,77.888 52.259,77.888 52.749,78.378 54.5,78.378 55.633,78.378 56,78.01 56,76.878 ; v1(52.883,30.201) 51.929,30.201 51.384,29.656 52.31,29.656 52.72,29.246 54.5,29.246 ; v1(52.883,79.832) 51.929,79.832 51.384,79.288 52.31,79.288 52.72,78.878 54.5,78.878 ; v1(53.67,39.167) 53.67,37.008 54.5,36.178 54.5,34.246 ; v1(53.67,88.798) 53.67,86.639 54.5,85.809 54.5,83.878 ; v1(53.696,43.078) 53.696,44.058 53.772,44.134 53.71,44.196 ; v1(53.696,92.71) 53.696,93.69 53.772,93.766 53.71,93.828 ; v1(54.661,39.167) 54.661,36.855 55.194,36.322 55.194,34.95 55.471,34.674 56.693,34.674 57,34.981 57,35.746 ; v1(54.661,88.798) 54.661,86.487 55.194,85.954 55.194,84.582 55.471,84.305 56.693,84.305 57,84.613 57,85.378 ; v1(54.96,43.084) 54.96,44.196 ; v1(54.96,92.716) 54.96,93.828 ; 55.01,22.733 55.01,23.768 cw(c56.363,23.768) 56.363,25.121 56.845,25.121 ccw(c56.845,26.276) 58,26.276 58,27.246 ; 55.01,72.365 55.01,73.4 cw(c56.363,73.4) 56.363,74.752 56.845,74.752 ccw(c56.845,75.907) 58,75.907 58,76.878 ; 55.383,38.1 55.55,37.933 55.55,37.16 56,36.71 56,35.746 ; 55.383,87.732 55.55,87.565 55.55,86.792 56,86.341 56,85.378 ; 55.536,38.1 v1(55.536,39.102) ; 55.536,87.732 v1(55.536,88.733) ; 56.5,35.746 56.5,36.714 56.936,37.149 56.936,37.948 ; 56.5,85.378 56.5,86.345 56.936,86.781 56.936,87.579 ; 56.783,38.1 56.936,37.948 ; 56.783,87.732 56.936,87.579 ; v1(56.947,39.141) 56.947,38.111 56.936,38.1 56.936,37.948 ; v1(56.947,88.773) 56.947,87.743 56.936,87.732 56.936,87.579 ; 57.41,22.733 57.41,23.882 cw(c58.191,23.882) 58.191,24.663 ccw(c58.191,24.972) 58.5,24.972 58.5,27.246 ; 57.41,72.365 57.41,73.514 cw(c58.191,73.514) 58.191,74.295 ccw(c58.191,74.604) 58.5,74.604 58.5,76.878 ; v1(58.699,22.9) 59.371,23.571 59.5,23.7 59.5,27.246 ; v1(58.699,72.531) 59.371,73.203 59.5,73.332 59.5,76.878 ; 59,27.246 59,24.736 58.17,23.905 58.17,22.272 58.395,22.047 59.371,22.047 ; 59,76.878 59,74.367 58.17,73.537 58.17,71.903 58.395,71.679 59.371,71.679 ; 60,27.246 60,25.293 60.771,24.522 60.771,23.571 ; 60,76.878 60,74.925 60.771,74.154 60.771,73.203 ; 60.5,27.246 60.5,25.987 62.357,24.13 62.357,21.946 63.105,21.946 ; 60.5,76.878 60.5,75.618 62.357,73.762 62.357,71.577 63.105,71.577 ; 61,27.246 61,26.452 63.054,24.398 63.054,23.597 63.054,22.925 63.246,22.733 65.924,22.733 ; 61,76.878 61,76.084 63.054,74.03 63.054,73.228 63.054,72.557 63.246,72.365 65.924,72.365 ; 61.5,27.246 v1@67.318,27.246 ; 61.5,76.878 v1@67.318,76.878 ; 62.224,39.387 62.547,39.71 63.899,39.71 64.142,39.954 v1(66.091,39.954) ; 62.224,89.019 62.547,89.342 63.899,89.342 64.142,89.586 v1(66.091,89.586) ; 63,28.746 63,28.16 63.271,27.889 v1(66.726,27.889) ; 63,29.246 63.03,29.275 66.305,29.275 71.984,23.597 74.676,23.597 76.333,21.94 77.404,21.94 ; 63,29.746 66.541,29.746 72.274,24.014 74.894,24.014 75.718,23.19 77.404,23.19 ; 63,30.246 66.748,30.246 72.555,24.439 77.404,24.439 ; 63,30.746 66.956,30.746 72.784,24.917 75.311,24.917 76.083,25.689 77.404,25.689 ; 63,31.746 66.9,31.746 67.737,32.584 67.737,44.313 ; 63,32.746 63.977,32.746 64.414,32.309 v1(66.65,32.309) ; 63,33.246 64.493,33.246 64.821,32.918 v1(67.158,32.918) ; 63,33.746 66.113,33.746 66.116,33.742 v1(67.194,33.742) ; 63,34.246 64.313,34.246 65.209,35.142 66.116,35.142 ; 63,78.378 63,77.792 63.271,77.521 v1(66.726,77.521) ; 63,78.878 63.03,78.907 66.305,78.907 71.984,73.228 74.676,73.228 76.333,71.571 77.404,71.571 ; 63,79.378 66.541,79.378 72.274,73.645 74.894,73.645 75.718,72.821 77.404,72.821 ; 63,79.878 66.748,79.878 72.555,74.071 77.404,74.071 ; 63,80.378 66.956,80.378 72.784,74.549 75.311,74.549 76.083,75.321 77.404,75.321 ; 63,81.378 66.9,81.378 67.737,82.215 67.737,93.945 ; 63,82.378 63.977,82.378 64.414,81.94 v1(66.65,81.94) ; 63,82.878 64.493,82.878 64.821,82.55 v1(67.158,82.55) ; 63,83.378 66.113,83.378 66.116,83.374 v1(67.194,83.374) ; 63,83.878 64.313,83.878 65.209,84.774 66.116,84.774 ; 63.105,20.345 63.105,20.546 64.505,21.946 ; 63.105,69.977 63.105,70.177 64.505,71.577 ; 65.924,22.098 65.924,22.733 ; 65.924,23.622 65.924,22.733 ; 65.924,71.73 65.924,72.365 ; 65.924,73.254 65.924,72.365 ; v1(67.513,31.496) 68.199,32.182 68.199,39.903 68.83,40.534 77.378,40.534 ; v1(67.513,81.128) 68.199,81.813 68.199,89.535 68.83,90.166 77.378,90.166 ; v1(68.656,31.445) 68.656,38.811 69.129,39.284 77.378,39.284 ; v1(68.656,81.077) 68.656,88.443 69.129,88.915 77.378,88.915 ; v1(68.682,29.82) 71.562,26.939 77.404,26.939 ; v1(68.682,79.451) 71.562,76.571 77.404,76.571 ; v1(69.723,29.642) 71.176,28.189 77.404,28.189 ; v1(69.723,79.273) 71.176,77.821 77.404,77.821
  Top Layer w0.381: 22.922,66.232 22.922,69.977 ; 27.254,71.577 27.254,69.952 28.575,68.631 28.575,63.475 ; 63.003,16.6 63.003,20.345 ; 63.003,66.232 63.003,69.977 ; 67.335,21.946 67.335,20.32 68.656,18.999 68.656,13.843 ; 67.335,71.577 67.335,69.952 68.656,68.631 68.656,63.475
  Top Layer w0.508: 20.69,73.203 21.488,73.203 21.692,73 21.692,68.682 ; v2(30.607,86.258) 30.607,80.772 32.308,79.071 37.323,79.071 ; 60.771,23.571 61.57,23.571 61.773,23.368 61.773,19.05 ; 60.771,73.203 61.57,73.203 61.773,73 61.773,68.682 ; v2(70.688,36.627) 70.688,31.14 72.389,29.439 77.404,29.439 ; v2(70.688,86.258) 70.688,80.772 72.389,79.071 77.404,79.071
  Top Layer w0.762: 5.598,77.689 2.372,77.689 0.991,79.07 0.991,82.702 1.372,83.083 5.74,83.083 7.696,85.039 7.696,90.957 8.585,91.846 26.406,91.846 ; v2(7.061,77.648) 7.061,75.895 ; v2(7.087,80.721) 7.112,80.747 7.112,81.585 9.22,83.693 9.271,83.693 9.271,90.221 9.644,90.594 20.742,90.594 20.742,89.019 20.742,87.716 21.092,87.366 25.004,87.366 v3(26.035,86.335) 26.035,84.774 ; 11.303,77.888 11.303,76.479 10.719,75.895 7.061,75.895 ; 16.129,93.828 v3(17.856,93.828) ; 21.692,68.682 7.747,68.682 7.061,69.367 7.061,75.895 ; 26.379,88.475 26.848,88.943 26.848,91.405 26.406,91.846 ; 26.406,93.945 26.406,91.846 ; 45.679,28.057 42.453,28.057 41.072,29.439 41.072,33.071 41.453,33.452 45.822,33.452 47.777,35.408 47.777,41.326 48.666,42.215 66.487,42.215 ; 45.679,77.689 42.453,77.689 41.072,79.07 41.072,82.702 41.453,83.083 45.822,83.083 47.777,85.039 47.777,90.957 48.666,91.846 66.487,91.846 ; v2(47.142,28.016) 47.142,26.264 ; v2(47.142,77.648) 47.142,75.895 ; v2(47.168,31.09) 47.193,31.115 47.193,31.953 49.301,34.061 49.352,34.061 49.352,40.589 49.725,40.962 60.824,40.962 60.824,39.387 60.824,38.084 61.173,37.734 65.085,37.734 v3(66.116,36.703) 66.116,35.142 ; v2(47.168,80.721) 47.193,80.747 47.193,81.585 49.301,83.693 49.352,83.693 49.352,90.221 49.725,90.594 60.824,90.594 60.824,89.019 60.824,87.716 61.173,87.366 65.085,87.366 v3(66.116,86.335) 66.116,84.774 ; 51.384,28.256 51.384,26.848 50.8,26.264 47.142,26.264 ; 51.384,77.888 51.384,76.479 50.8,75.895 47.142,75.895 ; 56.21,44.196 v3(57.937,44.196) ; 56.21,93.828 v3(57.937,93.828) ; 61.773,19.05 47.828,19.05 47.142,19.736 47.142,26.264 ; 61.773,68.682 47.828,68.682 47.142,69.367 47.142,75.895 ; 66.461,38.843 66.929,39.311 66.929,41.773 66.487,42.215 ; 66.461,88.475 66.929,88.943 66.929,91.405 66.487,91.846 ; 66.487,44.313 66.487,42.215 ; 66.487,93.945 66.487,91.846
  Top Layer w2.54: 12.319,63.435 17.653,63.435 ; 22.098,56.54 26.641,56.54 28.575,58.475 ; 52.4,13.803 57.734,13.803 ; 52.4,63.435 57.734,63.435 ; 62.179,6.909 66.722,6.909 68.656,8.843 ; 62.179,56.54 66.722,56.54 68.656,58.475
  Bottom Layer w0.254: v1(6.833,89.103) 6.833,89.052 6.858,89.027 v1(10.109,89.027) ; v1(6.858,88.392) 10.266,88.392 10.647,88.773 10.639,88.781 10.639,89.59 v1(10.541,89.687) ; v1(12.802,79.832) v1@12.852,79.781 ; v1(13.589,88.798) 13.589,92.634 13.64,92.685 v1(13.614,92.71) ; v1(14.58,88.798) 14.58,92.416 v1(14.879,92.716) ; v1(15.443,90.576) 15.454,90.565 v1(15.454,88.733) ; v1(16.866,88.773) 16.866,88.951 v1@16.916,89.002 ; v1@26.594,81.89 27.356,81.128 v1(27.432,81.128) ; v1(26.645,77.521) 28.575,79.451 v1(28.6,79.451) ; v1(27.076,82.55) 28.55,81.077 v1(28.575,81.077) ; v1(27.113,83.374) v1@27.127,83.388 ; v1(27.254,76.886) v1(29.642,79.273) ; v1(46.914,39.472) 46.914,39.421 46.939,39.395 v1(50.19,39.395) ; v1(46.914,89.103) 46.914,89.052 46.939,89.027 v1(50.19,89.027) ; v1(46.939,38.76) 50.347,38.76 50.728,39.141 50.72,39.149 50.72,39.958 v1(50.622,40.056) ; v1(46.939,88.392) 50.347,88.392 50.728,88.773 50.72,88.781 50.72,89.59 v1(50.622,89.687) ; v1(52.883,30.201) v1@52.934,30.15 ; v1(52.883,79.832) v1@52.934,79.781 ; v1(53.67,39.167) 53.67,43.002 53.721,43.053 v1(53.696,43.078) ; v1(53.67,88.798) 53.67,92.634 53.721,92.685 v1(53.696,92.71) ; v1(54.661,39.167) 54.661,42.785 v1(54.96,43.084) ; v1(54.661,88.798) 54.661,92.416 v1(54.96,92.716) ; v1(55.524,40.945) 55.536,40.934 v1(55.536,39.102) ; v1(55.524,90.576) 55.536,90.565 v1(55.536,88.733) ; v1(56.947,39.141) 56.947,39.319 v1@56.998,39.37 ; v1(56.947,88.773) 56.947,88.951 v1@56.998,89.002 ; v1@66.675,32.258 67.437,31.496 v1(67.513,31.496) ; v1@66.675,81.89 67.437,81.128 v1(67.513,81.128) ; v1(66.726,27.889) 68.656,29.82 v1(68.682,29.82) ; v1(66.726,77.521) 68.656,79.451 v1(68.682,79.451) ; v1(67.158,32.918) 68.631,31.445 v1(68.656,31.445) ; v1(67.158,82.55) 68.631,81.077 v1(68.656,81.077) ; v1(67.194,33.742) v1@67.208,33.757 ; v1(67.194,83.374) v1@67.208,83.388 ; v1(67.335,27.254) v1(69.723,29.642) ; v1(67.335,76.886) v1(69.723,79.273)
  Bottom Layer w0.762: v2(7.061,77.648) v2@7.087,77.673 ; v2@7.087,77.648 v2@7.087,77.673 ; v2(7.087,80.721) v2@7.087,77.673 ; v3(17.856,90.602) v3(17.856,93.828) ; v3(26.035,86.335) 30.531,86.335 v2(30.607,86.258) ; v2(47.142,28.016) v2@47.168,28.042 ; v2(47.142,77.648) v2@47.168,77.673 ; v2@47.168,28.016 v2@47.168,28.042 ; v2(47.168,31.09) v2@47.168,28.042 ; v2@47.168,77.648 v2@47.168,77.673 ; v2(47.168,80.721) v2@47.168,77.673 ; v3(57.937,40.97) v3(57.937,44.196) ; v3(57.937,90.602) v3(57.937,93.828) ; v3(66.116,36.703) 70.612,36.703 v2(70.688,36.627) ; v3(66.116,86.335) 70.612,86.335 v2(70.688,86.258)
  Bottom Layer w2.54: 12.319,58.435 19.115,58.435 24.155,63.475 28.575,63.475 ; 52.4,8.803 59.197,8.803 64.237,13.843 68.656,13.843 ; 52.4,58.435 59.197,58.435 64.237,63.475 68.656,63.475
  other v1: 66.599,18.999 65.405,19.025 69.444,19.38 45.06,19.964 48.997,20.853 50.267,20.853 51.791,20.853 53.315,20.853 54.585,20.853 56.109,20.853 57.633,20.853 69.444,20.904 43.129,21.006 45.06,21.234 71.45,21.514 73.025,21.514 75.006,21.514 69.444,22.428 43.129,22.53 45.06,22.758 69.444,23.698 50.267,24.155 51.791,24.155 53.315,24.155 48.997,24.181 45.06,24.282 53.315,25.425 54.585,25.425 63.475,26.34 64.999,26.34 66.523,26.34 67.793,26.34 42.647,26.568 43.993,26.695 53.315,26.949 54.585,26.949 51.181,31.445 52.578,31.445 77.419,32.334 72.339,32.487 77.419,33.604 72.339,33.757 77.419,35.128 72.339,35.281 77.419,36.652 43.205,36.754 72.339,36.805 43.205,38.024 43.205,39.548 64.059,40.691 63.17,40.716 43.205,41.072 63.17,41.402 64.084,41.402 46.609,43.561 47.879,43.561 49.403,43.561 50.927,43.561 52.095,46.457 53.365,46.457 54.889,46.457 56.413,46.457 64.313,46.736 65.583,46.736 67.107,46.736 68.631,46.736 26.518,68.631 66.599,68.631 25.324,68.656 65.405,68.656 29.362,69.012 69.444,69.012 4.978,69.596 45.06,69.596 8.915,70.485 10.185,70.485 11.709,70.485 13.233,70.485 14.503,70.485 16.027,70.485 17.551,70.485 48.997,70.485 50.267,70.485 51.791,70.485 53.315,70.485 54.585,70.485 56.109,70.485 57.633,70.485 29.362,70.536 69.444,70.536 3.048,70.637 43.129,70.637 4.978,70.866 45.06,70.866 31.369,71.145 32.944,71.145 34.925,71.145 71.45,71.145 73.025,71.145 75.006,71.145 29.362,72.06 69.444,72.06 3.048,72.161 43.129,72.161 4.978,72.39 45.06,72.39 29.362,73.33 69.444,73.33 10.185,73.787 11.709,73.787 13.233,73.787 50.267,73.787 51.791,73.787 53.315,73.787 8.915,73.812 48.997,73.812 4.978,73.914 45.06,73.914 13.233,75.057 14.503,75.057 53.315,75.057 54.585,75.057 23.393,75.971 24.917,75.971 26.441,75.971 27.711,75.971 63.475,75.971 64.999,75.971 66.523,75.971 67.793,75.971 2.565,76.2 42.647,76.2 3.912,76.327 43.993,76.327 13.233,76.581 14.503,76.581 53.315,76.581 54.585,76.581 11.1,81.077 12.497,81.077 51.181,81.077 52.578,81.077 37.338,81.966 77.419,81.966 32.258,82.118 72.339,82.118 37.338,83.236 77.419,83.236 32.258,83.388 72.339,83.388 37.338,84.76 77.419,84.76 32.258,84.912 72.339,84.912 37.338,86.284 77.419,86.284 3.124,86.385 43.205,86.385 32.258,86.436 72.339,86.436 3.124,87.655 43.205,87.655 3.124,89.179 43.205,89.179 23.978,90.322 64.059,90.322 23.089,90.348 63.17,90.348 3.124,90.703 43.205,90.703 23.089,91.034 24.003,91.034 63.17,91.034 64.084,91.034 6.528,93.193 7.798,93.193 9.322,93.193 10.846,93.193 46.609,93.193 47.879,93.193 49.403,93.193 50.927,93.193 12.014,96.088 13.284,96.088 14.808,96.088 16.332,96.088 52.095,96.088 53.365,96.088 54.889,96.088 56.413,96.088 24.232,96.368 25.502,96.368 27.026,96.368 28.55,96.368 64.313,96.368 65.583,96.368 67.107,96.368 68.631,96.368

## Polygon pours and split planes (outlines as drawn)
GND on Top Layer "GND_L01_P002" (solid, remove dead copper, pour order 2): 25.222,9.017 25.222,16.967 31.852,16.967 31.852,4.648 16.586,4.648 16.586,9.017
NetC9_2 on Top Layer "NETC9_2_L01_P000" (solid, remove dead copper, pour order 0): 8.89,17.018 8.89,10.973 23.114,10.973 23.114,17.018
GND on Top Layer "GND_L01_P014" (solid, remove dead copper, pour order 14): 1.499,18.288 38.506,18.288 38.506,48.082 38.532,48.108 1.499,48.108
GND on Top Layer "GND_L01_P016" (solid, remove dead copper, pour order 16): 21.361,42.164 21.412,42.215 25.781,42.215 26.162,42.215 27.026,41.351 26.695,41.021 26.695,37.948 21.361,37.948 21.336,37.973
no net on Top Layer "NONET_L01_P042" (solid, remove dead copper, pour order 42): 21.361,91.796 21.412,91.846 25.781,91.846 26.162,91.846 27.026,90.983 26.695,90.653 26.695,87.579 21.361,87.579 21.336,87.605
no net on Top Layer "NONET_L01_P044" (solid, remove dead copper, pour order 44): 1.499,67.92 38.506,67.92 38.506,97.714 38.532,97.739 1.499,97.739
no net on Top Layer "NONET_L01_P046" (solid, remove dead copper, pour order 46): 8.89,66.65 8.89,60.604 23.114,60.604 23.114,66.65
no net on Top Layer "NONET_L01_P048" (solid, remove dead copper, pour order 48): 25.222,58.649 25.222,66.599 31.852,66.599 31.852,54.28 16.586,54.28 16.586,58.649
no net on Top Layer "NONET_L01_P054" (solid, remove dead copper, pour order 54): 61.443,91.796 61.493,91.846 65.862,91.846 66.243,91.846 67.107,90.983 66.777,90.653 66.777,87.579 61.443,87.579 61.417,87.605
no net on Top Layer "NONET_L01_P056" (solid, remove dead copper, pour order 56): 41.58,67.92 78.588,67.92 78.588,97.714 78.613,97.739 41.58,97.739
no net on Top Layer "NONET_L01_P058" (solid, remove dead copper, pour order 58): 48.971,66.65 48.971,60.604 63.195,60.604 63.195,66.65
no net on Top Layer "NONET_L01_P060" (solid, remove dead copper, pour order 60): 65.303,58.649 65.303,66.599 71.933,66.599 71.933,54.28 56.667,54.28 56.667,58.649
no net on Top Layer "NONET_L01_P066" (solid, remove dead copper, pour order 66): 61.443,42.164 61.493,42.215 65.862,42.215 66.243,42.215 67.107,41.351 66.777,41.021 66.777,37.948 61.443,37.948 61.417,37.973
no net on Top Layer "NONET_L01_P068" (solid, remove dead copper, pour order 68): 41.58,18.288 78.588,18.288 78.588,48.082 78.613,48.108 41.58,48.108
no net on Top Layer "NONET_L01_P070" (solid, remove dead copper, pour order 70): 48.971,17.018 48.971,10.973 63.195,10.973 63.195,17.018
no net on Top Layer "NONET_L01_P072" (solid, remove dead copper, pour order 72): 65.303,9.017 65.303,16.967 71.933,16.967 71.933,4.648 56.667,4.648 56.667,9.017
VCC12V on Bottom Layer "VCC12V_L02_P010" (solid, remove dead copper, pour order 10): 8.915,11.455 8.915,5.436 20.396,5.436 26.111,11.151 31.191,11.151 31.191,17.018 23.216,17.018 17.653,11.455
GND on Bottom Layer "GND_L02_P012" (solid, remove dead copper, pour order 12): 1.499,18.288 38.506,18.288 38.506,48.082 38.532,48.108 1.499,48.108
no net on Bottom Layer "NONET_L02_P050" (solid, remove dead copper, pour order 50): 1.499,67.92 38.506,67.92 38.506,97.714 38.532,97.739 1.499,97.739
no net on Bottom Layer "NONET_L02_P052" (solid, remove dead copper, pour order 52): 8.915,61.087 8.915,55.067 20.396,55.067 26.111,60.782 31.191,60.782 31.191,66.65 23.216,66.65 17.653,61.087
no net on Bottom Layer "NONET_L02_P062" (solid, remove dead copper, pour order 62): 41.58,67.92 78.588,67.92 78.588,97.714 78.613,97.739 41.58,97.739
no net on Bottom Layer "NONET_L02_P064" (solid, remove dead copper, pour order 64): 48.997,61.087 48.997,55.067 60.477,55.067 66.192,60.782 71.272,60.782 71.272,66.65 63.297,66.65 57.734,61.087
no net on Bottom Layer "NONET_L02_P074" (solid, remove dead copper, pour order 74): 41.58,18.288 78.588,18.288 78.588,48.082 78.613,48.108 41.58,48.108
no net on Bottom Layer "NONET_L02_P076" (solid, remove dead copper, pour order 76): 48.997,11.455 48.997,5.436 60.477,5.436 66.192,11.151 71.272,11.151 71.272,17.018 63.297,17.018 57.734,11.455

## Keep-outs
Keep-Out Layer:
  lines w0.254: 0,0 40,0 40,49.5 0,49.5 0,0 ; 0,49.632 0,99.132 40,99.132 40,49.632 0,49.632 ; 40.081,0 40.081,49.5 80.081,49.5 80.081,0 40.081,0 ; 40.081,49.632 40.081,99.132 80.081,99.132 80.081,49.632 40.081,49.632

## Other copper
Top Layer:
  rectangle net GND: 30.175,16.51 31.166,18.796
  rectangle: 30.175,66.142 31.166,68.428
  rectangle: 70.256,66.142 71.247,68.428
  rectangle: 70.256,16.51 71.247,18.796

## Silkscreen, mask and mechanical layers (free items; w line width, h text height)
Top Overlay:
  lines w0.254: -5.105,97.663 -4.597,99.187 ; -5.08,1.524 -4.572,0 ; -4.851,99.187 -4.343,99.187 ; -4.826,0 -4.318,0 ; -4.587,57.49 -4.597,99.187 ; -4.583,41.697 -4.572,0 ; -4.089,97.663 -4.597,99.187 ; -4.064,1.524 -4.572,0 ; 0,-4.826 0,-4.318 ; 1.524,-5.08 0,-4.572 ; 1.524,-4.064 0,-4.572 ; 32.286,-4.582 0,-4.572 ; 47.826,-4.587 80.112,-4.597 ; 78.587,-5.105 80.112,-4.597 ; 78.588,-4.089 80.112,-4.597 ; 80.112,-4.851 80.112,-4.343
  text "99.187 (mm)" at -5.501,57.236 h1.52 r270.01
  text "80.112 (mm)" at 32.539,-5.496 h1.52 r359.98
